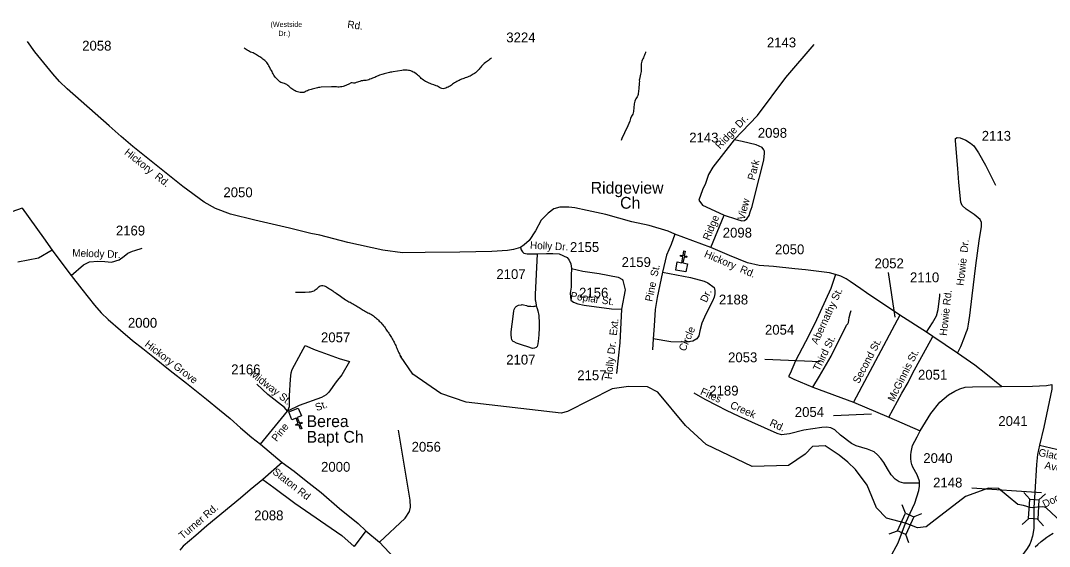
# Model space of a CAD drawing. Extents: x 1364363 to 1407445, y 538563 to 573342.
# Drawn here: x 1379893 to 1392969, y 565370 to 572055 of the extents above; entities that cross this region are included whole.
import ezdxf

# ---------------------------------------------------------------- set-up
doc = ezdxf.new("R2010")
doc.units = 0
for name, color, linetype in [('Exist Cultural Church CELL', 7, 'Continuous'), ('Exist Cultural Church Label', 7, 'Continuous'), ('Exist Cultural Church with Cemetery Label', 7, 'Continuous'), ('Exist Hydrographic Creek Single Shore', 7, 'Continuous'), ('Exist Railroad Mainline', 7, 'Continuous'), ('Exist Road Secondary Structure Standard Bridge CELL', 7, 'Continuous'), ('Exist Road Secondary Type 51 Attributed', 7, 'Continuous'), ('Exist Road Secondary Type 51 Label', 7, 'Continuous'), ('Exist Road Secondary Type 51 Number Label', 7, 'Continuous')]:
    doc.layers.add(name, color=color, linetype=linetype)

msp = doc.modelspace()

# ---------------------------------------------------------------- linework, layer by layer
at = {"layer": 'Exist Cultural Church CELL'}
for points in [[(1388240, 568987), (1388296, 568977), (1388310, 569052), (1388279, 569058), (1388281, 569073), (1388313, 569068), (1388324, 569127), (1388339, 569124), (1388329, 569065), (1388360, 569059), (1388357, 569043), (1388326, 569049), (1388312, 568974), (1388369, 568964), (1388350, 568859), (1388221, 568882)], [(1383462, 567029), (1383409, 567008), (1383438, 566937), (1383468, 566949), (1383473, 566935), (1383444, 566923), (1383466, 566867), (1383451, 566861), (1383429, 566917), (1383399, 566905), (1383393, 566919), (1383423, 566931), (1383394, 567002), (1383341, 566981), (1383301, 567079), (1383422, 567128)]]:
    msp.add_lwpolyline(points, close=True, dxfattribs=at)
at = {"layer": 'Exist Hydrographic Creek Single Shore'}
for points in [[(1384357, 571318), (1384348, 571315), (1384333, 571308), (1384318, 571303), (1384302, 571298), (1384286, 571294), (1384270, 571292), (1384253, 571291), (1384237, 571290), (1384221, 571287), (1384205, 571282), (1384189, 571277), (1384174, 571271), (1384158, 571266), (1384143, 571261), (1384126, 571260), (1384109, 571262), (1384093, 571262), (1384066, 571248), (1384006, 571223), (1383991, 571218), (1383975, 571214), (1383959, 571211), (1383942, 571210), (1383926, 571210), (1383910, 571211), (1383844, 571211), (1383713, 571208), (1383697, 571206), (1383681, 571203), (1383665, 571199), (1383649, 571195), (1383633, 571191), (1383617, 571187), (1383601, 571183), (1383585, 571178), (1383569, 571174), (1383554, 571169), (1383538, 571163), (1383524, 571156), (1383509, 571148), (1383494, 571142), (1383478, 571140), (1383461, 571141), (1383445, 571141), (1383428, 571143), (1383413, 571148), (1383397, 571153), (1383383, 571161), (1383368, 571169), (1383355, 571178), (1383341, 571187), (1383328, 571197), (1383316, 571208), (1383304, 571220), (1383291, 571230), (1383278, 571240), (1383264, 571247), (1383248, 571253), (1383232, 571258), (1383216, 571263), (1383202, 571269), (1383188, 571278), (1383176, 571289), (1383164, 571301), (1383141, 571324), (1383130, 571336), (1383119, 571349), (1383110, 571362), (1383102, 571377), (1383096, 571392), (1383089, 571407), (1383081, 571422), (1383071, 571437), (1383056, 571466), (1383048, 571481), (1383039, 571495), (1383030, 571508), (1383021, 571522), (1383011, 571535), (1382999, 571547), (1382986, 571556), (1382973, 571566), (1382959, 571575), (1382946, 571584), (1382932, 571593), (1382918, 571602), (1382905, 571611), (1382891, 571620), (1382877, 571629), (1382862, 571637), (1382848, 571643), (1382832, 571648), (1382817, 571655), (1382803, 571662), (1382788, 571670), (1382774, 571679), (1382761, 571688), (1382747, 571697), (1382733, 571706)], [(1385877, 571582), (1385866, 571570), (1385854, 571559), (1385842, 571548), (1385828, 571538), (1385814, 571529), (1385800, 571521), (1385787, 571511), (1385775, 571500), (1385764, 571488), (1385753, 571476), (1385742, 571463), (1385731, 571451), (1385721, 571439), (1385710, 571426), (1385699, 571414), (1385687, 571403), (1385674, 571392), (1385661, 571383), (1385647, 571373), (1385633, 571365), (1385619, 571357), (1385605, 571349), (1385590, 571342), (1385574, 571336), (1385559, 571331), (1385543, 571326), (1385528, 571320), (1385513, 571314), (1385497, 571308), (1385482, 571302), (1385467, 571295), (1385453, 571288), (1385438, 571280), (1385424, 571272), (1385410, 571263), (1385396, 571254), (1385383, 571245), (1385369, 571235), (1385355, 571227), (1385341, 571218), (1385327, 571210), (1385312, 571203), (1385297, 571196), (1385282, 571191), (1385265, 571189), (1385249, 571192), (1385233, 571197), (1385218, 571203), (1385205, 571213), (1385190, 571220), (1385175, 571226), (1385144, 571236), (1385114, 571247), (1385099, 571253), (1385084, 571260), (1385054, 571275), (1385039, 571282), (1385025, 571290), (1385012, 571299), (1384999, 571309), (1384986, 571320), (1384974, 571331), (1384962, 571342), (1384950, 571353), (1384937, 571364), (1384925, 571374), (1384898, 571393), (1384884, 571401), (1384869, 571408), (1384854, 571414), (1384838, 571418), (1384822, 571422), (1384806, 571424), (1384789, 571425), (1384773, 571425), (1384756, 571423), (1384740, 571421), (1384628, 571403), (1384612, 571400), (1384596, 571397), (1384580, 571393), (1384564, 571390), (1384548, 571386), (1384532, 571383), (1384516, 571379), (1384500, 571375), (1384484, 571371), (1384454, 571361), (1384439, 571354), (1384424, 571347), (1384409, 571340), (1384394, 571333), (1384379, 571327), (1384364, 571321), (1384357, 571318)], [(1387837, 571659), (1387834, 571643), (1387828, 571628), (1387822, 571613), (1387815, 571598), (1387808, 571583), (1387800, 571568), (1387794, 571552), (1387788, 571537), (1387784, 571522), (1387781, 571506), (1387780, 571489), (1387780, 571473), (1387781, 571456), (1387781, 571440), (1387781, 571423), (1387780, 571407), (1387772, 571375), (1387759, 571312), (1387757, 571296), (1387758, 571279), (1387757, 571263), (1387749, 571182), (1387747, 571166), (1387745, 571149), (1387743, 571133), (1387741, 571117), (1387737, 571101), (1387730, 571086), (1387721, 571072), (1387712, 571058), (1387704, 571044), (1387698, 571029), (1387695, 571013), (1387692, 570997), (1387690, 570980), (1387689, 570964), (1387688, 570947), (1387686, 570931), (1387685, 570914), (1387682, 570898), (1387680, 570882), (1387673, 570867), (1387664, 570854), (1387656, 570839), (1387645, 570808), (1387635, 570778), (1387611, 570717), (1387569, 570629), (1387535, 570555), (1387528, 570532)], [(1383386, 568604), (1383396, 568603), (1383413, 568602), (1383429, 568601), (1383445, 568601), (1383462, 568601), (1383478, 568601), (1383495, 568602), (1383511, 568602), (1383560, 568605), (1383577, 568607), (1383593, 568610), (1383609, 568614), (1383623, 568621), (1383637, 568630), (1383650, 568640), (1383663, 568650), (1383676, 568661), (1383688, 568672), (1383701, 568682), (1383717, 568686), (1383733, 568686), (1383750, 568684), (1383764, 568677), (1383779, 568669), (1383793, 568661), (1383807, 568652), (1383821, 568644), (1383835, 568635), (1383849, 568626), (1383863, 568617), (1383876, 568608), (1383890, 568599), (1383904, 568590), (1383958, 568553), (1384024, 568506), (1384038, 568497), (1384052, 568489), (1384066, 568481), (1384081, 568473), (1384095, 568465), (1384109, 568457), (1384124, 568449), (1384138, 568441), (1384152, 568433), (1384167, 568425), (1384181, 568417), (1384195, 568408), (1384209, 568400), (1384223, 568391), (1384236, 568381), (1384249, 568372), (1384263, 568363), (1384278, 568355), (1384292, 568348), (1384307, 568340), (1384322, 568333), (1384336, 568325), (1384351, 568317), (1384365, 568309), (1384378, 568300), (1384392, 568290), (1384404, 568280), (1384417, 568269), (1384429, 568258), (1384441, 568247), (1384452, 568235), (1384464, 568223), (1384475, 568211), (1384486, 568199), (1384497, 568186), (1384507, 568174), (1384517, 568160), (1384526, 568147), (1384535, 568133), (1384545, 568120), (1384554, 568106), (1384563, 568093), (1384572, 568079), (1384581, 568065), (1384590, 568052), (1384599, 568038), (1384608, 568024), (1384616, 568010), (1384625, 567996), (1384632, 567981), (1384640, 567967), (1384647, 567952), (1384654, 567937), (1384661, 567922), (1384668, 567907), (1384674, 567892), (1384680, 567877), (1384686, 567862), (1384693, 567847), (1384700, 567832), (1384707, 567817), (1384714, 567802), (1384722, 567788), (1384730, 567774)], [(1393186, 565620), (1392928, 565859), (1392907, 565869), (1392880, 565873), (1392816, 565867), (1392754, 565862), (1392725, 565865), (1392640, 565892), (1392566, 565901), (1392321, 566106), (1392195, 566109), (1391901, 566006), (1391478, 565680), (1391402, 565620), (1391293, 565608), (1391142, 565665), (1390897, 565728), (1390773, 565862), (1390654, 566150), (1390505, 566349), (1390408, 566440), (1390295, 566531), (1390119, 566650), (1389959, 566639), (1389863, 566542), (1389652, 566400), (1389192, 566386), (1388605, 566667), (1388343, 566905), (1387994, 567329), (1387862, 567397), (1387620, 567402), (1387411, 567374), (1386846, 567086), (1386763, 567062), (1385557, 567204), (1385234, 567313), (1384880, 567559), (1384722, 567788)]]:
    msp.add_lwpolyline(points, dxfattribs=at)
at = {"layer": 'Exist Railroad Mainline'}
msp.add_lwpolyline([(1392790, 565363), (1392823, 565394), (1392866, 565431), (1392900, 565459), (1392937, 565487), (1392961, 565503), (1393015, 565540)], dxfattribs=at)
at = {"layer": 'Exist Road Secondary Structure Standard Bridge CELL'}
for p, q in [((1392645, 566056), (1392720, 565971)), ((1392920, 566039), (1392835, 565964)), ((1391139, 565794), (1391099, 565900)), ((1391242, 565747), (1391348, 565788)), ((1392706, 565724), (1392622, 565649)), ((1392819, 565717), (1392894, 565632)), ((1390931, 565528), (1391037, 565568)), ((1391183, 565415), (1391143, 565520))]:
    msp.add_line(p, q, dxfattribs=at)
for points in [[(1392835, 565964), (1392820, 565717), (1392704, 565724), (1392720, 565971)], [(1391037, 565568), (1391138, 565794), (1391244, 565747), (1391143, 565520)]]:
    msp.add_lwpolyline(points, close=True, dxfattribs=at)
at = {"layer": 'Exist Road Secondary Type 51 Attributed'}
for p, q in [((1388665, 569170), (1388837, 569579)), ((1388665, 569170), (1388210, 569339)), ((1391406, 568095), (1391070, 568308)), ((1391489, 568037), (1391406, 568095)), ((1391801, 567827), (1391489, 568037)), ((1389964, 567393), (1390481, 567202)), ((1390481, 567202), (1390927, 567015)), ((1382942, 566670), (1383284, 567090)), ((1390927, 567015), (1391327, 566841)), ((1382942, 566670), (1383218, 566438)), ((1383218, 566438), (1382971, 566219)), ((1384283, 565568), (1384133, 565370)), ((1384283, 565568), (1384455, 565422))]:
    msp.add_line(p, q, dxfattribs=at)
for points in [[(1380304, 571377), (1380074, 571656), (1379979, 571788)], [(1388963, 570537), (1389258, 570850), (1389618, 571330), (1389979, 571752)], [(1386247, 569172), (1386158, 569146), (1386083, 569130), (1385884, 569119), (1385477, 569112), (1385035, 569107), (1384746, 569103), (1384499, 569137), (1384051, 569235), (1383696, 569325), (1383583, 569350), (1383311, 569416), (1382871, 569518), (1382561, 569595), (1382372, 569667), (1382228, 569746), (1381957, 569947), (1381321, 570454), (1381172, 570579), (1381019, 570718), (1380484, 571187), (1380388, 571281), (1380304, 571377)], [(1388963, 570537), (1388693, 570193), (1388636, 570099), (1388597, 569982), (1388561, 569904), (1388514, 569771)], [(1388837, 569579), (1388991, 569530), (1389059, 569511), (1389093, 569513), (1389125, 569534), (1389152, 569577), (1389164, 569622), (1389191, 569693), (1389225, 569833), (1389338, 570281), (1389348, 570369), (1389348, 570395), (1389341, 570413), (1389317, 570442), (1389242, 570477), (1389065, 570517), (1388963, 570537)], [(1391801, 567827), (1391842, 567910), (1391891, 568029), (1391913, 568088), (1391924, 568118), (1391931, 568144), (1391942, 568197), (1391958, 568304), (1391986, 568557), (1392034, 568942), (1392076, 569253), (1392106, 569435), (1392106, 569486), (1392087, 569526), (1392012, 569589), (1391910, 569656), (1391859, 569705), (1391844, 569745), (1391819, 569995), (1391806, 570174), (1391776, 570525), (1391777, 570556), (1391797, 570569), (1391834, 570565), (1391906, 570534), (1391967, 570497), (1392009, 570462), (1392066, 570374), (1392157, 570215), (1392283, 569961)], [(1388514, 569771), (1388558, 569707), (1388661, 569662), (1388837, 569579)], [(1379912, 569670), (1379651, 569577), (1379428, 569514), (1379262, 569476), (1379150, 569465), (1379058, 569478), (1378873, 569536), (1378617, 569580)], [(1379912, 569670), (1380185, 569293), (1380296, 569136)], [(1388210, 569339), (1388125, 569379), (1387884, 569451), (1387661, 569495), (1387331, 569588), (1387094, 569641), (1386938, 569675), (1386862, 569682), (1386748, 569683), (1386672, 569660), (1386597, 569608), (1386511, 569517), (1386436, 569383), (1386356, 569258), (1386294, 569203), (1386247, 569172)], [(1388210, 569339), (1388161, 569208), (1388104, 569074), (1388050, 568855)], [(1380296, 569136), (1380120, 569036), (1379858, 568983)], [(1380296, 569136), (1380429, 568955), (1380534, 568815)], [(1380534, 568815), (1380692, 568949), (1380768, 568988), (1380876, 568995), (1380963, 568992), (1381047, 568985), (1381147, 569014), (1381208, 569061), (1381258, 569099), (1381315, 569123), (1381345, 569131), (1381437, 569162)], [(1386247, 569172), (1386254, 569139), (1386271, 569114), (1386288, 569096), (1386331, 569090), (1386457, 569088)], [(1386457, 569088), (1386435, 568573), (1386435, 568503), (1386436, 568490), (1386440, 568461), (1386445, 568439), (1386448, 568430)], [(1386457, 569088), (1386578, 569095), (1386656, 569092), (1386740, 569088), (1386838, 569043), (1386865, 569007), (1386885, 568962), (1386897, 568901)], [(1390252, 568827), (1390174, 568847), (1389969, 568872), (1389871, 568884), (1389733, 568900), (1389462, 568930), (1389282, 568940), (1389132, 568973), (1388903, 569070), (1388665, 569170)], [(1386897, 568901), (1386889, 568813), (1386889, 568664), (1386880, 568588), (1386885, 568500), (1386921, 568476), (1386975, 568455), (1387056, 568438), (1387403, 568389), (1387530, 568384)], [(1386897, 568901), (1387038, 568870), (1387245, 568840), (1387490, 568791), (1387542, 568762), (1387548, 568751)], [(1388050, 568855), (1387983, 568534), (1387960, 568381), (1387946, 568175), (1387933, 568009)], [(1388050, 568855), (1388407, 568788), (1388580, 568740), (1388626, 568720), (1388710, 568661), (1388718, 568623), (1388718, 568581), (1388709, 568540), (1388687, 568486), (1388603, 568321)], [(1390252, 568827), (1390192, 568648), (1389988, 568205), (1389871, 567970), (1389743, 567729), (1389673, 567568), (1389653, 567528), (1389722, 567497), (1389964, 567393)], [(1391070, 568308), (1390644, 568595), (1390573, 568643), (1390435, 568738), (1390386, 568773), (1390320, 568805), (1390252, 568827)], [(1380534, 568815), (1380672, 568640), (1380831, 568436), (1380917, 568340), (1381008, 568255), (1381161, 568118), (1381316, 567986), (1381446, 567884), (1381594, 567769), (1381793, 567606), (1382003, 567444), (1382255, 567241), (1382423, 567107), (1382558, 566995), (1382688, 566877), (1382832, 566753), (1382942, 566670)], [(1387548, 568751), (1387575, 568633), (1387530, 568384)], [(1391406, 568095), (1391482, 568212), (1391536, 568303), (1391556, 568380), (1391575, 568556), (1391575, 568582)], [(1386166, 568381), (1386171, 568392), (1386181, 568406), (1386191, 568418), (1386199, 568425), (1386206, 568429), (1386222, 568436), (1386258, 568443), (1386270, 568444), (1386284, 568441), (1386321, 568431), (1386342, 568426), (1386380, 568422), (1386412, 568421), (1386421, 568422), (1386432, 568424), (1386448, 568430)], [(1386448, 568430), (1386459, 568393), (1386467, 568363), (1386481, 568306), (1386486, 568206), (1386484, 568147), (1386481, 568061), (1386470, 567977), (1386469, 567948), (1386466, 567944), (1386458, 567910), (1386446, 567897), (1386426, 567891), (1386401, 567888), (1386338, 567905), (1386271, 567929), (1386209, 567948), (1386198, 567952)], [(1386198, 567952), (1386165, 567970), (1386154, 567977), (1386141, 567988), (1386136, 568000), (1386131, 568019), (1386129, 568064), (1386129, 568099), (1386153, 568293), (1386161, 568364), (1386166, 568381)], [(1387530, 568384), (1387509, 567956), (1387467, 567569)], [(1388603, 568321), (1388553, 568206), (1388527, 568109), (1388513, 568047), (1388488, 568008), (1388438, 567979), (1388354, 567968), (1388158, 567972), (1387933, 568009)], [(1389964, 567393), (1390047, 567534), (1390196, 567790), (1390388, 568184), (1390406, 568199), (1390414, 568217), (1390421, 568244), (1390425, 568282), (1390441, 568342), (1390451, 568371)], [(1391070, 568308), (1390999, 568181), (1390481, 567202)], [(1390927, 567015), (1391093, 567319), (1391172, 567454), (1391229, 567567), (1391489, 568037)], [(1383284, 567090), (1383304, 567129), (1383310, 567149), (1383309, 567284), (1383323, 567497), (1383331, 567575), (1383345, 567617), (1383457, 567829), (1383510, 567923), (1383635, 567870), (1383711, 567843)], [(1387933, 568009), (1387926, 567869)], [(1383711, 567843), (1383943, 567759), (1384072, 567721), (1383974, 567551)], [(1392359, 567404), (1392159, 567562), (1392021, 567674), (1391801, 567827)], [(1383974, 567551), (1383905, 567461), (1383812, 567329), (1383776, 567296), (1383718, 567264), (1383435, 567160), (1383284, 567090)], [(1383284, 567090), (1383249, 567134), (1383037, 567300), (1382896, 567431)], [(1391327, 566841), (1391464, 567061), (1391577, 567205), (1391688, 567296), (1391766, 567344), (1391831, 567375), (1391899, 567393), (1391990, 567400), (1392359, 567404)], [(1392359, 567404), (1392756, 567409), (1392933, 567417), (1393000, 567429)], [(1393000, 567429), (1392998, 567367), (1392899, 566886), (1392841, 566656)], [(1391316, 566174), (1391212, 566173), (1391120, 566176), (1391058, 566191), (1391009, 566223), (1390958, 566281), (1390911, 566357), (1390865, 566436), (1390827, 566488), (1390782, 566536), (1390740, 566571), (1390659, 566606), (1390513, 566649), (1390455, 566678), (1390314, 566785), (1390240, 566850), (1390189, 566878), (1390135, 566885), (1390077, 566883), (1389849, 566848), (1389667, 566799), (1389563, 566788), (1389510, 566806), (1389028, 567023), (1388867, 567099), (1388752, 567158), (1388593, 567236), (1388452, 567317)], [(1384455, 565422), (1384779, 565727), (1384835, 565814), (1384848, 565870), (1384844, 565958), (1384695, 566846)], [(1391316, 566174), (1391316, 566200), (1391290, 566278), (1391235, 566378), (1391220, 566411), (1391213, 566447), (1391209, 566488), (1391206, 566533), (1391212, 566570), (1391230, 566654), (1391287, 566762), (1391327, 566841)], [(1392841, 566656), (1392818, 566537), (1392804, 566413), (1392782, 566056), (1392770, 565863)], [(1392841, 566656), (1393133, 566589), (1393225, 566572), (1393290, 566546), (1393333, 566501), (1393403, 566389), (1393432, 566289)], [(1383218, 566438), (1383369, 566326), (1383521, 566202), (1383712, 566055), (1383946, 565852), (1384182, 565662), (1384283, 565568)], [(1382971, 566219), (1382813, 566089), (1382687, 565984), (1382262, 565631), (1382121, 565507), (1381960, 565372), (1381919, 565324)], [(1382971, 566219), (1383111, 566120), (1383378, 565919), (1383977, 565507), (1384133, 565370)], [(1391142, 565665), (1391257, 565919), (1391311, 566082), (1391318, 566136), (1391316, 566174)], [(1392770, 565863), (1392770, 565596), (1392755, 565500), (1392734, 565434), (1392719, 565397), (1392687, 565342), (1392605, 565234), (1392457, 565040), (1392431, 565008), (1392400, 564959), (1392385, 564935), (1392394, 564894)], [(1388794, 563066), (1389005, 563210), (1389203, 563367), (1389444, 563548), (1389928, 563890), (1390263, 564144), (1390412, 564261), (1390475, 564347), (1390534, 564423), (1390603, 564560), (1390941, 565221), (1391045, 565414), (1391142, 565665)], [(1384455, 565422), (1384888, 564964), (1385080, 564775), (1385191, 564653), (1385272, 564544)]]:
    msp.add_lwpolyline(points, dxfattribs=at)
at = {"layer": 'Exist Road Secondary Type 51 Number Label'}
for p, q in [((1391009, 568283), (1390925, 568852)), ((1390055, 567715), (1389353, 567744)), ((1390708, 567052), (1390223, 567032)), ((1392867, 566052), (1391985, 566111))]:
    msp.add_line(p, q, dxfattribs=at)

# ---------------------------------------------------------------- texts
at = {"layer": 'Exist Cultural Church Label'}
for s, p in [('Ridgeview', (1387139, 569854)), ('Ch', (1387513, 569663))]:
    msp.add_text(s, height=150, rotation=0, dxfattribs=at).set_placement(p)
at = {"layer": 'Exist Cultural Church with Cemetery Label'}
for s, p in [('Berea', (1383528, 566887)), ('Bapt Ch', (1383528, 566688))]:
    msp.add_text(s, height=150, dxfattribs=at).set_placement(p)
at = {"layer": 'Exist Road Secondary Type 51 Label'}
for s, p in [('(Westside', (1383069, 571974)), ('    Dr.)', (1383069, 571859))]:
    msp.add_text(s, height=65.6, dxfattribs=at).set_placement(p)
for s, rotation, p in [('Rd.', 352.6299, (1384042, 571962)), ('Ridge Dr.', 46.7415, (1388781, 570415)), ('Hickory  Rd.', 321.4755, (1381204, 570363)), ('View       Park', 75.8088, (1389093, 569512)), ('Ridge', 67.2192, (1388646, 569252)), ('Holly Dr.', 357.3954, (1386366, 569154)), ('Howie  Dr.', 83.5106, (1391879, 568680)), ('Melody Dr.', 358.2091, (1380548, 569055)), ('Hickory  Rd.', 336.9511, (1388573, 569054)), ('Pine  St.', 78.2565, (1387921, 568476)), ('Poplar St.', 351.834, (1386877, 568514)), ('Circle          Dr.', 66.3668, (1388340, 567842)), ('Abernathy St.', 65.2886, (1390020, 567930)), ('Howie Rd.', 83.6517, (1391664, 568044)), ('Holly Dr.  Ext.', 83.7645, (1387409, 567492)), ('Hickory Grove ', 322.3819, (1381462, 567923)), ('Third St.', 64.0171, (1390043, 567590)), ('Second St.', 62.1052, (1390547, 567431)), ('McGinnis St.', 63.4999, (1390992, 567202)), ('Midway St.', 321.7644, (1382803, 567547)), ('Fites    Creek      Rd.', 335.74, (1388523, 567305)), ('St.', 20.0971, (1383657, 567088)), ('Pine', 50.8803, (1383147, 566694)), ('Gladdis', 349.0195, (1392824, 566521)), ('Staton Rd', 321.863, (1383087, 566301)), (' Ave.', 349.0195, (1392867, 566366)), ('Dogwood', 26.3331, (1392909, 565859)), ('Turner Rd.', 40.4508, (1381953, 565455))]:
    msp.add_text(s, height=95, rotation=rotation, dxfattribs=at).set_placement(p)
at = {"layer": 'Exist Road Secondary Type 51 Number Label'}
for s, p in [('3224', (1386066, 571778)), ('2143', (1389378, 571714)), ('2058', (1380676, 571673)), ('2098', (1389263, 570565)), ('2113', (1392109, 570527)), ('2143', (1388391, 570505)), ('2050', (1382471, 569809)), ('2169', (1381104, 569323)), ('2098', (1388817, 569296)), ('2155', (1386875, 569113)), ('2050', (1389482, 569084)), ('2159', (1387532, 568922)), ('2052', (1390747, 568906)), ('2107', (1385940, 568769)), ('2110', (1391197, 568728)), ('2156', (1386991, 568533)), ('2188', (1388768, 568446)), ('2000', (1381257, 568150)), ('2054', (1389354, 568062)), ('2057', (1383711, 567965)), ('2107', (1386065, 567682)), ('2053', (1388885, 567711)), ('2166', (1382570, 567558)), ('2157', (1386968, 567483)), ('2051', (1391299, 567490)), ('2189', (1388646, 567288)), ('2054', (1389733, 567016)), ('2041', (1392320, 566901)), ('2056', (1384863, 566574)), ('2040', (1391366, 566430)), ('2000', (1383712, 566319)), ('2148', (1391491, 566119)), ('2088', (1382862, 565702))]:
    msp.add_text(s, height=125, dxfattribs=at).set_placement(p)

doc.saveas('drawing.dxf')
